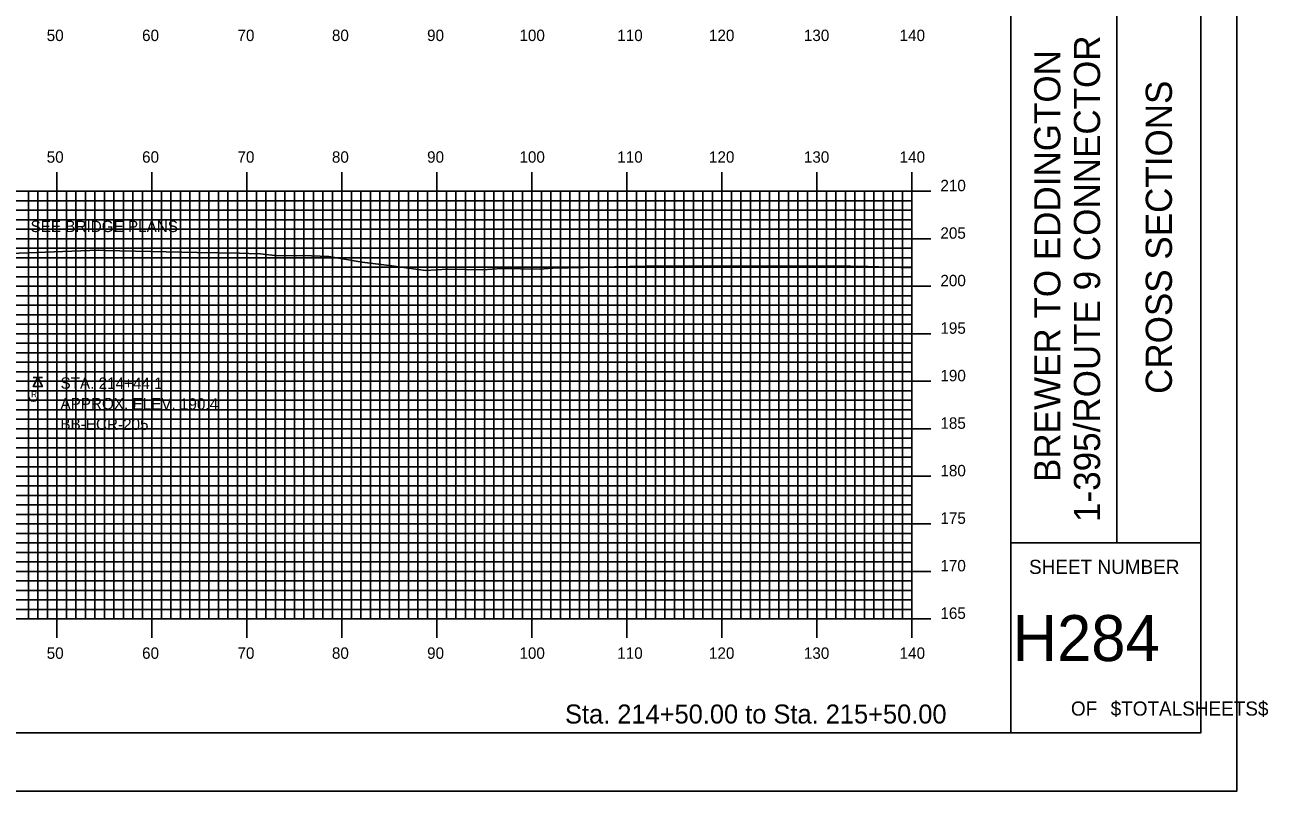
# Model space of a CAD drawing. Extents: x 1796027 to 1796370, y 442591 to 442811.
# Drawn here: x 1796239 to 1796369.9, y 442590.5 to 442671.2 of the extents above; entities that cross this region are included whole.
import ezdxf

# ---------------------------------------------------------------- set-up
doc = ezdxf.new("R2010")
doc.units = 0
for name, color, linetype in [('ANNOTATION', 7, 'Continuous'), ('BORDER', 7, 'Continuous'), ('BORING - REFUSAL', 7, 'Continuous'), ('H_V ANNOTATION', 7, 'Continuous'), ('MAJOR', 7, 'Continuous'), ('MINOR', 7, 'Continuous'), ('PLOT BOUNDARY', 7, 'Continuous'), ('S_Roadway_Centerline', 7, 'Continuous')]:
    doc.layers.add(name, color=color, linetype=linetype)

msp = doc.modelspace()

# ---------------------------------------------------------------- linework, layer by layer
at = {"layer": 'BORDER'}
for p, q in [((1796342.79, 442596.67), (1796342.79, 442806.67)), ((1796353.97, 442616.67), (1796353.97, 442686.67)), ((1796342.79, 442616.67), (1796362.79, 442616.67))]:
    msp.add_line(p, q, dxfattribs=at)
msp.add_lwpolyline([(1796042.79, 442596.67), (1796362.79, 442596.67), (1796362.79, 442806.67), (1796042.79, 442806.67)], close=True, dxfattribs=at)
at = {"layer": 'BORING - REFUSAL'}
for p, q in [((1796240.87, 442634.07), (1796239.91, 442634.07)), ((1796240.39, 442633.11), (1796240.39, 442632.05))]:
    msp.add_line(p, q, dxfattribs=at)
msp.add_lwpolyline([(1796240.39, 442634.07), (1796240.87, 442633.11), (1796239.91, 442633.11)], close=True, dxfattribs=at)
msp.add_arc((1796239.91, 442632.05), 0.485, 180, 0, dxfattribs=at)
at = {"layer": 'MAJOR'}
for p, q in [((1796242.39, 442655.67), (1796242.39, 442653.67)), ((1796252.39, 442655.67), (1796252.39, 442653.67)), ((1796262.39, 442655.67), (1796262.39, 442653.67)), ((1796272.39, 442655.67), (1796272.39, 442653.67)), ((1796282.39, 442655.67), (1796282.39, 442653.67)), ((1796292.39, 442655.67), (1796292.39, 442653.67)), ((1796302.39, 442655.67), (1796302.39, 442653.67)), ((1796312.39, 442655.67), (1796312.39, 442653.67)), ((1796322.39, 442655.67), (1796322.39, 442653.67)), ((1796332.39, 442655.67), (1796332.39, 442653.67)), ((1796052.39, 442653.67), (1796332.39, 442653.67)), ((1796052.39, 442653.67), (1796332.39, 442653.67)), ((1796242.39, 442608.67), (1796242.39, 442653.67)), ((1796252.39, 442608.67), (1796252.39, 442653.67)), ((1796262.39, 442608.67), (1796262.39, 442653.67)), ((1796272.39, 442608.67), (1796272.39, 442653.67)), ((1796282.39, 442608.67), (1796282.39, 442653.67)), ((1796292.39, 442608.67), (1796292.39, 442653.67)), ((1796302.39, 442608.67), (1796302.39, 442653.67)), ((1796312.39, 442608.67), (1796312.39, 442653.67)), ((1796322.39, 442608.67), (1796322.39, 442653.67)), ((1796334.4, 442653.67), (1796330.39, 442653.67)), ((1796332.39, 442608.67), (1796332.39, 442653.67)), ((1796332.39, 442608.67), (1796332.39, 442653.67)), ((1796052.39, 442648.67), (1796332.39, 442648.67)), ((1796334.4, 442648.67), (1796330.39, 442648.67)), ((1796052.39, 442643.67), (1796332.39, 442643.67)), ((1796334.4, 442643.67), (1796330.39, 442643.67)), ((1796052.39, 442638.67), (1796332.39, 442638.67)), ((1796334.4, 442638.67), (1796330.39, 442638.67)), ((1796052.39, 442633.67), (1796332.39, 442633.67)), ((1796334.4, 442633.67), (1796330.39, 442633.67)), ((1796052.39, 442628.67), (1796332.39, 442628.67)), ((1796334.4, 442628.67), (1796330.39, 442628.67)), ((1796052.39, 442623.67), (1796332.39, 442623.67)), ((1796334.4, 442623.67), (1796330.39, 442623.67)), ((1796052.39, 442618.67), (1796332.39, 442618.67)), ((1796334.4, 442618.67), (1796330.39, 442618.67)), ((1796052.39, 442613.67), (1796332.39, 442613.67)), ((1796334.4, 442613.67), (1796330.39, 442613.67)), ((1796052.39, 442608.67), (1796332.39, 442608.67)), ((1796052.39, 442608.67), (1796332.39, 442608.67)), ((1796242.39, 442606.66), (1796242.39, 442608.67)), ((1796252.39, 442606.66), (1796252.39, 442608.67)), ((1796262.39, 442606.66), (1796262.39, 442608.67)), ((1796272.39, 442606.66), (1796272.39, 442608.67)), ((1796282.39, 442606.66), (1796282.39, 442608.67)), ((1796292.39, 442606.66), (1796292.39, 442608.67)), ((1796302.39, 442606.66), (1796302.39, 442608.67)), ((1796312.39, 442606.66), (1796312.39, 442608.67)), ((1796322.39, 442606.66), (1796322.39, 442608.67)), ((1796334.4, 442608.67), (1796330.39, 442608.67)), ((1796332.39, 442606.66), (1796332.39, 442608.67))]:
    msp.add_line(p, q, dxfattribs=at)
at = {"layer": 'MINOR'}
for p, q in [((1796239.39, 442608.67), (1796239.39, 442653.67)), ((1796240.39, 442608.67), (1796240.39, 442653.67)), ((1796241.39, 442608.67), (1796241.39, 442653.67)), ((1796243.39, 442608.67), (1796243.39, 442653.67)), ((1796244.39, 442608.67), (1796244.39, 442653.67)), ((1796245.39, 442608.67), (1796245.39, 442653.67)), ((1796246.39, 442608.67), (1796246.39, 442653.67)), ((1796247.39, 442608.67), (1796247.39, 442653.67)), ((1796248.39, 442608.67), (1796248.39, 442653.67)), ((1796249.39, 442608.67), (1796249.39, 442653.67)), ((1796250.39, 442608.67), (1796250.39, 442653.67)), ((1796251.39, 442608.67), (1796251.39, 442653.67)), ((1796253.39, 442608.67), (1796253.39, 442653.67)), ((1796254.39, 442608.67), (1796254.39, 442653.67)), ((1796255.39, 442608.67), (1796255.39, 442653.67)), ((1796256.39, 442608.67), (1796256.39, 442653.67)), ((1796257.39, 442608.67), (1796257.39, 442653.67)), ((1796258.39, 442608.67), (1796258.39, 442653.67)), ((1796259.39, 442608.67), (1796259.39, 442653.67)), ((1796260.39, 442608.67), (1796260.39, 442653.67)), ((1796261.39, 442608.67), (1796261.39, 442653.67)), ((1796263.39, 442608.67), (1796263.39, 442653.67)), ((1796264.39, 442608.67), (1796264.39, 442653.67)), ((1796265.39, 442608.67), (1796265.39, 442653.67)), ((1796266.39, 442608.67), (1796266.39, 442653.67)), ((1796267.39, 442608.67), (1796267.39, 442653.67)), ((1796268.39, 442608.67), (1796268.39, 442653.67)), ((1796269.39, 442608.67), (1796269.39, 442653.67)), ((1796270.39, 442608.67), (1796270.39, 442653.67)), ((1796271.39, 442608.67), (1796271.39, 442653.67)), ((1796273.39, 442608.67), (1796273.39, 442653.67)), ((1796274.39, 442608.67), (1796274.39, 442653.67)), ((1796275.39, 442608.67), (1796275.39, 442653.67)), ((1796276.39, 442608.67), (1796276.39, 442653.67)), ((1796277.39, 442608.67), (1796277.39, 442653.67)), ((1796278.39, 442608.67), (1796278.39, 442653.67)), ((1796279.39, 442608.67), (1796279.39, 442653.67)), ((1796280.39, 442608.67), (1796280.39, 442653.67)), ((1796281.39, 442608.67), (1796281.39, 442653.67)), ((1796283.39, 442608.67), (1796283.39, 442653.67)), ((1796284.39, 442608.67), (1796284.39, 442653.67)), ((1796285.39, 442608.67), (1796285.39, 442653.67)), ((1796286.39, 442608.67), (1796286.39, 442653.67)), ((1796287.39, 442608.67), (1796287.39, 442653.67)), ((1796288.39, 442608.67), (1796288.39, 442653.67)), ((1796289.39, 442608.67), (1796289.39, 442653.67)), ((1796290.39, 442608.67), (1796290.39, 442653.67)), ((1796291.39, 442608.67), (1796291.39, 442653.67)), ((1796293.39, 442608.67), (1796293.39, 442653.67)), ((1796294.39, 442608.67), (1796294.39, 442653.67)), ((1796295.39, 442608.67), (1796295.39, 442653.67)), ((1796296.39, 442608.67), (1796296.39, 442653.67)), ((1796297.39, 442608.67), (1796297.39, 442653.67)), ((1796298.39, 442608.67), (1796298.39, 442653.67)), ((1796299.39, 442608.67), (1796299.39, 442653.67)), ((1796300.39, 442608.67), (1796300.39, 442653.67)), ((1796301.39, 442608.67), (1796301.39, 442653.67)), ((1796303.39, 442608.67), (1796303.39, 442653.67)), ((1796304.39, 442608.67), (1796304.39, 442653.67)), ((1796305.39, 442608.67), (1796305.39, 442653.67)), ((1796306.39, 442608.67), (1796306.39, 442653.67)), ((1796307.39, 442608.67), (1796307.39, 442653.67)), ((1796308.39, 442608.67), (1796308.39, 442653.67)), ((1796309.39, 442608.67), (1796309.39, 442653.67)), ((1796310.39, 442608.67), (1796310.39, 442653.67)), ((1796311.39, 442608.67), (1796311.39, 442653.67)), ((1796313.39, 442608.67), (1796313.39, 442653.67)), ((1796314.39, 442608.67), (1796314.39, 442653.67)), ((1796315.39, 442608.67), (1796315.39, 442653.67)), ((1796316.39, 442608.67), (1796316.39, 442653.67)), ((1796317.39, 442608.67), (1796317.39, 442653.67)), ((1796318.39, 442608.67), (1796318.39, 442653.67)), ((1796319.39, 442608.67), (1796319.39, 442653.67)), ((1796320.39, 442608.67), (1796320.39, 442653.67)), ((1796321.39, 442608.67), (1796321.39, 442653.67)), ((1796323.39, 442608.67), (1796323.39, 442653.67)), ((1796324.39, 442608.67), (1796324.39, 442653.67)), ((1796325.39, 442608.67), (1796325.39, 442653.67)), ((1796326.39, 442608.67), (1796326.39, 442653.67)), ((1796327.39, 442608.67), (1796327.39, 442653.67)), ((1796328.39, 442608.67), (1796328.39, 442653.67)), ((1796329.39, 442608.67), (1796329.39, 442653.67)), ((1796330.39, 442608.67), (1796330.39, 442653.67)), ((1796331.39, 442608.67), (1796331.39, 442653.67)), ((1796052.39, 442652.67), (1796332.39, 442652.67)), ((1796332.39, 442652.67), (1796330.39, 442652.67)), ((1796052.39, 442651.67), (1796332.39, 442651.67)), ((1796332.39, 442651.67), (1796330.39, 442651.67)), ((1796052.39, 442650.67), (1796332.39, 442650.67)), ((1796052.39, 442649.67), (1796332.39, 442649.67)), ((1796332.39, 442650.67), (1796330.39, 442650.67)), ((1796332.39, 442649.67), (1796330.39, 442649.67)), ((1796052.39, 442647.67), (1796332.39, 442647.67)), ((1796332.39, 442647.67), (1796330.39, 442647.67)), ((1796052.39, 442646.67), (1796332.39, 442646.67)), ((1796052.39, 442645.67), (1796332.39, 442645.67)), ((1796332.39, 442646.67), (1796330.39, 442646.67)), ((1796332.39, 442645.67), (1796330.39, 442645.67)), ((1796052.39, 442644.67), (1796332.39, 442644.67)), ((1796332.39, 442644.67), (1796330.39, 442644.67)), ((1796052.39, 442642.67), (1796332.39, 442642.67)), ((1796052.39, 442641.67), (1796332.39, 442641.67)), ((1796332.39, 442642.67), (1796330.39, 442642.67)), ((1796332.39, 442641.67), (1796330.39, 442641.67)), ((1796052.39, 442640.67), (1796332.39, 442640.67)), ((1796332.39, 442640.67), (1796330.39, 442640.67)), ((1796052.39, 442639.67), (1796332.39, 442639.67)), ((1796332.39, 442639.67), (1796330.39, 442639.67)), ((1796052.39, 442637.67), (1796332.39, 442637.67)), ((1796052.39, 442636.67), (1796332.39, 442636.67)), ((1796332.39, 442637.67), (1796330.39, 442637.67)), ((1796332.39, 442636.67), (1796330.39, 442636.67)), ((1796052.39, 442635.67), (1796332.39, 442635.67)), ((1796332.39, 442635.67), (1796330.39, 442635.67)), ((1796052.39, 442634.67), (1796332.39, 442634.67)), ((1796332.39, 442634.67), (1796330.39, 442634.67)), ((1796052.39, 442632.67), (1796332.39, 442632.67)), ((1796332.39, 442632.67), (1796330.39, 442632.67)), ((1796052.39, 442631.67), (1796332.39, 442631.67)), ((1796332.39, 442631.67), (1796330.39, 442631.67)), ((1796052.39, 442630.67), (1796332.39, 442630.67)), ((1796332.39, 442630.67), (1796330.39, 442630.67)), ((1796052.39, 442629.67), (1796332.39, 442629.67)), ((1796332.39, 442629.67), (1796330.39, 442629.67)), ((1796052.39, 442627.67), (1796332.39, 442627.67)), ((1796332.39, 442627.67), (1796330.39, 442627.67)), ((1796052.39, 442626.67), (1796332.39, 442626.67)), ((1796332.39, 442626.67), (1796330.39, 442626.67)), ((1796052.39, 442625.67), (1796332.39, 442625.67)), ((1796052.39, 442624.67), (1796332.39, 442624.67)), ((1796332.39, 442625.67), (1796330.39, 442625.67)), ((1796332.39, 442624.67), (1796330.39, 442624.67)), ((1796052.39, 442622.67), (1796332.39, 442622.67)), ((1796332.39, 442622.67), (1796330.39, 442622.67)), ((1796052.39, 442621.67), (1796332.39, 442621.67)), ((1796332.39, 442621.67), (1796330.39, 442621.67)), ((1796052.39, 442620.67), (1796332.39, 442620.67)), ((1796052.39, 442619.67), (1796332.39, 442619.67)), ((1796332.39, 442620.67), (1796330.39, 442620.67)), ((1796332.39, 442619.67), (1796330.39, 442619.67)), ((1796052.39, 442617.67), (1796332.39, 442617.67)), ((1796332.39, 442617.67), (1796330.39, 442617.67)), ((1796052.39, 442616.67), (1796332.39, 442616.67)), ((1796052.39, 442615.67), (1796332.39, 442615.67)), ((1796332.39, 442616.67), (1796330.39, 442616.67)), ((1796332.39, 442615.67), (1796330.39, 442615.67)), ((1796052.39, 442614.67), (1796332.39, 442614.67)), ((1796332.39, 442614.67), (1796330.39, 442614.67)), ((1796052.39, 442612.67), (1796332.39, 442612.67)), ((1796052.39, 442611.67), (1796332.39, 442611.67)), ((1796332.39, 442612.67), (1796330.39, 442612.67)), ((1796332.39, 442611.67), (1796330.39, 442611.67)), ((1796052.39, 442610.67), (1796332.39, 442610.67)), ((1796332.39, 442610.67), (1796330.39, 442610.67)), ((1796052.39, 442609.67), (1796332.39, 442609.67)), ((1796332.39, 442609.67), (1796330.39, 442609.67))]:
    msp.add_line(p, q, dxfattribs=at)
at = {"layer": 'PLOT BOUNDARY'}
msp.add_lwpolyline([(1796026.61, 442590.55), (1796366.61, 442590.55), (1796366.61, 442810.55), (1796026.61, 442810.55)], close=True, dxfattribs=at)
at = {"layer": 'S_Roadway_Centerline'}
msp.add_lwpolyline([(1796234.75, 442647), (1796243.02, 442647.33), (1796246.81, 442647.45), (1796247.41, 442647.42), (1796257.17, 442647.23), (1796261.62, 442647.14), (1796262.6, 442647.13), (1796263.83, 442647.07), (1796265.31, 442646.91), (1796267.64, 442646.86), (1796268.29, 442646.9), (1796271.03, 442646.8), (1796274.09, 442646.26), (1796274.52, 442646.2), (1796277.66, 442645.81), (1796281.21, 442645.34), (1796283.5, 442645.46), (1796287.19, 442645.39), (1796289.21, 442645.53), (1796293.16, 442645.48), (1796294.61, 442645.56), (1796304.3, 442645.77), (1796313.5, 442645.77), (1796324.14, 442645.81), (1796327.76, 442645.75), (1796332.39, 442645.6)], dxfattribs=at)

# ---------------------------------------------------------------- texts
at = {"layer": 'ANNOTATION'}
msp.add_text('SEE BRIDGE PLANS', height=1.2, dxfattribs=at).set_placement((1796239.62, 442649.37))
at = {"layer": 'BORDER'}
for s, p in [('1-395/ROUTE 9 CONNECTOR', (1796352.2, 442618.87)), ('BREWER TO EDDINGTON', (1796348.02, 442623.07)), ('CROSS SECTIONS', (1796359.76, 442632.34))]:
    msp.add_text(s, height=2.7557, rotation=90, dxfattribs=at).set_placement(p)
for s, height, p in [('SHEET NUMBER', 1.4905, (1796344.72, 442613.4)), ('H284', 4.839, (1796343, 442604.23)), ('OF', 1.491, (1796349.13, 442598.49)), ('$TOTALSHEETS$', 1.4905, (1796353.31, 442598.49))]:
    msp.add_text(s, height=height, dxfattribs=at).set_placement(p)
at = {"layer": 'BORING - REFUSAL'}
for s, p in [('STA. 214+44.1', (1796242.77, 442632.89)), ('APPROX. ELEV. 190.4', (1796242.77, 442630.73)), ('BB-ECR-205', (1796242.76, 442628.57))]:
    msp.add_text(s, height=1.2, rotation=359.8142, dxfattribs=at).set_placement(p)
msp.add_text('R', height=0.64, dxfattribs=at).set_placement((1796239.68, 442631.99))
at = {"layer": 'H_V ANNOTATION'}
for s, height, p in [('50', 1.2, (1796241.32, 442669.47)), ('60', 1.2, (1796251.36, 442669.47)), ('70', 1.2, (1796261.4, 442669.47)), ('80', 1.2, (1796271.34, 442669.47)), ('90', 1.2, (1796281.36, 442669.47)), ('100', 1.2, (1796291.08, 442669.47)), ('110', 1.2, (1796301.38, 442669.47)), ('120', 1.2, (1796311.03, 442669.47)), ('130', 1.2, (1796321.02, 442669.47)), ('140', 1.2, (1796331.1, 442669.47)), ('50', 1.2, (1796241.32, 442656.67)), ('60', 1.2, (1796251.36, 442656.67)), ('70', 1.2, (1796261.4, 442656.67)), ('80', 1.2, (1796271.34, 442656.67)), ('90', 1.2, (1796281.36, 442656.67)), ('100', 1.2, (1796291.08, 442656.67)), ('110', 1.2, (1796301.38, 442656.67)), ('120', 1.2, (1796311.03, 442656.67)), ('130', 1.2, (1796321.02, 442656.67)), ('140', 1.2, (1796331.1, 442656.67)), ('210', 1.2, (1796335.39, 442653.67)), ('205', 1.2, (1796335.39, 442648.67)), ('200', 1.2, (1796335.39, 442643.67)), ('195', 1.2, (1796335.39, 442638.67)), ('190', 1.2, (1796335.39, 442633.67)), ('185', 1.2, (1796335.39, 442628.67)), ('180', 1.2, (1796335.39, 442623.67)), ('175', 1.2, (1796335.39, 442618.67)), ('170', 1.2, (1796335.39, 442613.67)), ('165', 1.2, (1796335.39, 442608.67)), ('50', 1.2, (1796241.32, 442604.47)), ('60', 1.2, (1796251.36, 442604.47)), ('70', 1.2, (1796261.4, 442604.47)), ('80', 1.2, (1796271.34, 442604.47)), ('90', 1.2, (1796281.36, 442604.47)), ('100', 1.2, (1796291.08, 442604.47)), ('110', 1.2, (1796301.38, 442604.47)), ('120', 1.2, (1796311.03, 442604.47)), ('130', 1.2, (1796321.02, 442604.47)), ('140', 1.2, (1796331.1, 442604.47)), ('Sta. 214+50.00 to Sta. 215+50.00', 2.0004, (1796295.88, 442597.66))]:
    msp.add_text(s, height=height, dxfattribs=at).set_placement(p)
at = {"layer": 'S_Roadway_Centerline'}
for s, p in [('C', (1796246.8, 442647.45)), ('C', (1796246.8, 442647.45)), ('L', (1796246.81, 442647.44)), ('L', (1796246.81, 442647.44))]:
    msp.add_text(s, height=0.0146, dxfattribs=at).set_placement(p)

doc.saveas('drawing.dxf')
